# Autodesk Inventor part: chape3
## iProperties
Created: 2009-03
Part Number: chape3
Document SubType Name: Modeling
Designer: Ordi1
Author: Ordi1
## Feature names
1. Extrusion1
2. Chanfrein1 [Chamfer]
3. Perçage3 [Hole]
4. Perçage4 [Hole]
